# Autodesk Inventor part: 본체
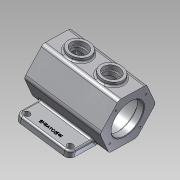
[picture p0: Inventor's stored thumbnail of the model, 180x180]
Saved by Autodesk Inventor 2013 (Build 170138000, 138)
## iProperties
Created: 2021-06
Part Number: 본체
Material: 알루미늄 6061
Document SubType Name: Modeling
Designer: hana
Density: 2.71 g/cm^3
Mass: 1500.81 g
Surface Area: 1102.36 cm^2
Volume: 553.806 cm^3
Author: hana
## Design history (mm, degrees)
sketch "스케치1" dims "d0" = 105
  geometry: L1 (52.5, 0)-(26.25, -45.466); L2 (26.25, -45.466)-(-26.25, -45.466); L3 (-26.25, -45.466)-(-52.5, 0); L4 (-52.5, 0)-(-26.25, 45.466); L5 (-26.25, 45.466)-(26.25, 45.466); L6 (26.25, 45.466)-(52.5, 0); 3 further points
  constraints: 12 end point, 2 coincident, 2 horizontal alignment, 15 other
extrude "돌출1" new body sketch "스케치1" stored distance "d1" = 140; taper "d2" = 0 deg
node "작업 평면1"
sketch "스케치2"
  geometry: L1 (73.5, 0)-(-73.5, 0) reference; L2 (0, -98)-(0, 98) reference; L3 (-107.676, -71.784)-(107.676, 71.784); L4 (107.676, -71.784)-(-107.676, 71.784); L5 (-75, -55)-(75, -55); L6 (75, -55)-(75, 45); L7 (75, 45)-(-75, 45); L8 (-75, 45)-(-75, -55); L9 (26.25, -70)-(-26.25, -70) reference; L10 (-26.25, 70)-(26.25, 70) reference; 1 further point
  constraints: 12 end point, 2 midpoint, 2 parallel, 1 horizontal, 1 perpendicular, 1 other
  dimensions: "d7" = 100 distance between parallel lines of L7 L5; "d9" = 150 distance between parallel lines of L6 L8; "d107" = 25 distance between parallel lines of L7 L10
extrude "돌출2" join sketch "스케치2" distance "d11" = 12; taper "d12" = 0 deg
node "작업 평면2"
sketch "스케치4"
  geometry: L1 (105, 0)-(-105, 0) reference; L2 (0, -98)-(0, 98) reference; L3 (-26.25, 70)-(26.25, 70) reference; C1 r 20 at (0, 30); C2 r 20 at (0, -30); 1 further point
  constraints: 2 centre point, 2 point on line
  dimensions: "d17" = 40 diameter of C1; "d18" = 40 diameter of C2; "d19" = 60 distance of C2.centre C1.centre; "d20" = 40 distance from line of C1.centre L3
extrude "돌출4" join sketch "스케치4" stored distance "d21" = 12; taper "d22" = 0 deg
sketch "스케치5"
  geometry: L1 (0, 128)-(0, -68) reference; L2 (-105, 30)-(105, 30) reference; C1 r 20 at (0, 0) reference; C2 r 20 at (0, 60) reference; C3 r 15 at (0, 0); C4 r 15 at (0, 60); 1 further point
  constraints: 2 centre point, 2 coincident
  dimensions: "d23" = 30 diameter of C3; "d24" = 30 diameter of C4
extrude "돌출5" cut sketch "스케치5" distance "d25" = 8; taper "d26" = 0 deg
fillet "모깎기1" dims "d33" = 10
sketch "스케치9"
  geometry: C1 r 5.5 at (65, -35); C2 r 5.5 at (65, 45); A1 r 10 centre (65, 45) between (75, 45) and (65, 55) reference; A2 r 10 centre (65, -35) between (65, -45) and (75, -35) reference; 1 further point
  constraints: 2 centre point, 2 coincident
  dimensions: "d34" = 11 diameter of C1; "d35" = 11 diameter of C2
extrude "돌출8" cut sketch "스케치9" stored distance "d36" = 8; taper "d37" = 0 deg
sketch "스케치10"
  geometry: L1 (0, -98)-(0, 98) reference; L2 (-70.5, 0)-(73, 0) reference; L3 (45.466, 70)-(0, 70) reference; L4 (0, 70)-(30, 70); L5 (30, 70)-(30, 58); L6 (30, 58)-(37.5, 58); L7 (37.5, 58)-(37.5, -58); L8 (37.5, -58)-(30, -58); L9 (0, -70)-(45.466, -70) reference; L10 (30, -58)-(30, -70); L11 (30, -70)-(0, -70); L12 (0, 70)-(0, -70); 1 further point
  constraints: 16 end point, 4 perpendicular, 2 parallel, 2 point on line, 1 collinear
  dimensions: "d38" = 12 distance between parallel lines of L6 L3; "d39" = 12 distance between parallel lines of L9 L8; "d40" = 60 diameter of L5 L1; "d41" = 60 diameter of L10 L1; "d42" = 75 diameter of L7 L1
revolve "회전1" sketch "스케치10" stored, may be unused: angle "d43" = 90 deg
sketch "스케치11"
  geometry: C1 r 15 at (0, 0) reference; C2 r 12.5 at (0, 0); 1 further point
  constraints: 1 centre point, 1 coincident
  dimensions: "d44" = 25 diameter of C2
extrude "돌출9" cut sketch "스케치11" stored distance "d45" = 8; taper "d46" = 0 deg
sketch "스케치12"
  geometry: C1 r 15 at (0, 0) reference; C2 r 12.5 at (0, 0); 1 further point
  constraints: 1 centre point, 1 coincident
  dimensions: "d47" = 25 diameter of C2
extrude "돌출10" cut sketch "스케치12" stored distance "d48" = 8; taper "d49" = 0 deg
sketch "스케치13" dims "d50" = 80
  geometry: L1 (0, 0)-(28.284, 28.284); L2 (-105, 0)-(105, 0) reference; C1 r 30 at (0, 0) reference; 1 further point
  constraints: 2 coincident, 2 end point, 3 other
  dimensions: "d51" = 45 deg angle of L1 L2
hole "구멍1" sketch "스케치13" at (28.284, 28.284) diameter "d53" = 3.242; stored, may be unused: countersink angle "d57" = 90 deg, drill point angle "d59" = 118 deg; dims "d54" = 8, "d55" = 4, "d56" = 2, "d58" = 10
fillet "모깎기2" dims "d63" = 5
fillet "모깎기3" dims "d64" = 8
fillet "모깎기4" dims "d65" = 3
fillet "모깎기5" dims "d66" = 3
chamfer "모따기1" distance "d67" = 1; stored, may be unused: second distance "d68" = 2, angle "d69" = 45 deg
sketch "스케치14"
  geometry: L1 (-65, -45)-(-32.293, -45) reference; L2 (-75, 45)-(-75, -35) reference; 2 further points
  constraints: 1 other
  dimensions: "d70" = 50 distance from line of point (-61, 5) L1; "d71" = 14 distance from line of point (-61, 5) L2
feature "엠보싱1" sketch "스케치14" dims "d11" = 12, "d12" = 0, "d72" = 0.5, "d73" = 0
sketch "스케치17" dims "d96" = 80
  geometry: C1 r 31 at (0, 0) reference; 2 further points
  constraints: 2 horizontal alignment, 1 coincident, 2 other
hole "구멍4" sketch "스케치17" at (40, 0) diameter "d97" = 3.242; stored, may be unused: countersink angle "d101" = 90 deg, drill point angle "d103" = 118 deg; dims "d98" = 8, "d99" = 4, "d100" = 2, "d102" = 10
chamfer "모따기2" distance "d108" = 1; stored, may be unused: second distance "d109" = 2, angle "d110" = 45 deg
node "솔리드1"
mirror "대칭1"
pattern_circular "원형 패턴1" dims angle "d61" = 360 deg
pattern_circular "원형 패턴2" dims angle "d105" = 360 deg
node "투영된 루프1"
other parameters: "d16" = 52.5
